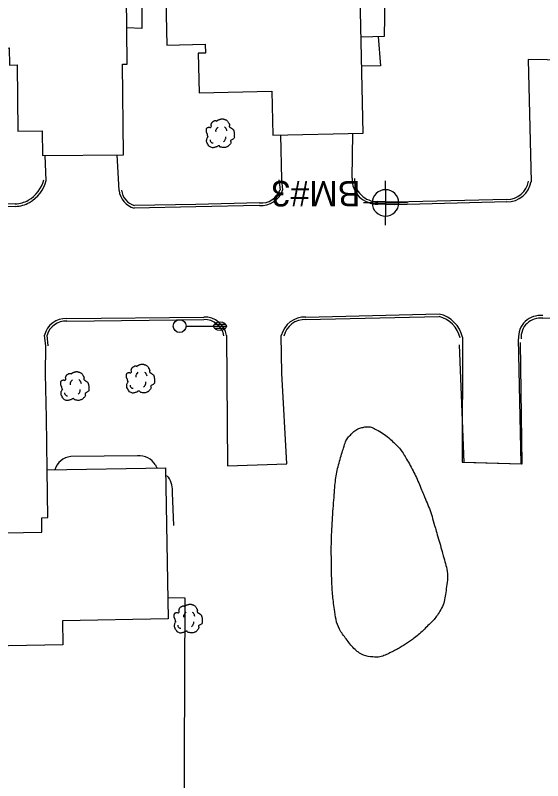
# Model space of a CAD drawing. Extents: x 2145380 to 2156929, y 139568 to 149130.
# Drawn here: x 2150403.3 to 2150527.5, y 144116.2 to 144296.4 of the extents above; entities that cross this region are included whole.
import ezdxf

# ---------------------------------------------------------------- set-up
doc = ezdxf.new("R2010")
doc.units = 0
for name, color, linetype in [('SURV_Benchmark', 7, 'Continuous'), ('SURV_Text', 7, 'Continuous'), ('TOPO_Asphalt', 7, 'Continuous'), ('TOPO_Building', 7, 'Continuous'), ('TOPO_Concrete', 7, 'Continuous'), ('TOPO_Curb Back', 7, 'Continuous'), ('TOPO_Fence', 7, 'Continuous'), ('TOPO_Light Pole', 7, 'Continuous'), ('TOPO_Tree', 7, 'Continuous'), ('TOPO_Tree Line', 7, 'Continuous'), ('TOPO_Wall Freestanding', 7, 'Continuous')]:
    doc.layers.add(name, color=color, linetype=linetype)

# ---------------------------------------------------------------- blocks, each defined once
blk = doc.blocks.new('LP')
at = {"layer": 'TOPO_Light Pole'}
blk.add_line((3.81, 0), (20.32, 0), dxfattribs=at)
for points in [[(20.32, 0), (27.94, 0)], [(20.32, 0), (23.5, 0)], [(20.83, 1.27), (27.43, 1.27)], [(20.83, 1.27), (23.5, 1.27)], [(23.71, 1.27), (27.43, 1.27)], [(23.71, 0), (27.94, 0)], [(20.83, -1.27), (27.43, -1.27)], [(20.83, -1.27), (23.5, -1.27)], [(23.71, -1.27), (27.43, -1.27)]]:
    blk.add_lwpolyline(points, dxfattribs=at)
blk.add_circle((0, 0), 3.81, dxfattribs=at)
blk.add_ellipse((24.13, 0), major_axis=(3.81, 0), ratio=0.666667, dxfattribs=at)
blk = doc.blocks.new('TREE')
at = {"layer": 'TOPO_Tree'}
for points in [[(-14.07, -0.4), (-14.17, 0.5), (-14.37, 1.38), (-14.6, 2.25), (-14.84, 3.17), (-15.47, 3.96), (-15.66, 4.9), (-15.8, 5.59), (-15.71, 6.31), (-15.66, 7.01), (-15.6, 7.91), (-15.72, 8.8), (-15.13, 9.66), (-14.62, 10.42), (-13.76, 10.49), (-13.02, 10.72), (-12.18, 10.98), (-11.06, 10), (-10.37, 10.72), (-9.4, 11.74), (-10.29, 13.28), (-9.84, 14.42), (-9.56, 15.15), (-9.32, 15.89), (-8.78, 16.54), (-8.18, 17.26), (-7.5, 17.68), (-6.67, 18.13), (-6.14, 18.41), (-5.61, 18.61), (-5.08, 18.66), (-4.55, 18.71), (-4.02, 18.54), (-3.49, 18.13)], [(-3.49, 17.6), (-3.07, 18.27), (-2.58, 18.8), (-1.9, 19.19), (-1.05, 19.68), (-0.19, 19.96), (0.74, 20.24), (1.62, 20.51), (2.51, 20.82), (3.39, 20.77), (4.1, 20.73), (4.8, 20.47), (5.51, 20.24), (6.43, 19.95), (7.32, 19.73), (8.15, 19.19), (9.36, 18.4), (10.02, 17.21), (10.8, 16.01), (11.24, 15.33), (11.58, 14.62), (11.86, 13.89), (12.17, 13.08), (11.37, 12.02), (11.86, 11.25), (12, 11.03), (12.18, 10.86), (12.39, 10.72), (12.91, 10.35), (13.45, 10.02), (13.97, 9.66), (14.7, 9.16), (15.41, 8.68), (16.09, 8.07), (16.7, 7.53), (16.93, 6.73), (17.15, 5.95), (17.59, 4.38), (17.71, 2.77), (17.68, 1.19), (17.65, -0.25), (17.83, -2.22), (16.62, -3.04), (15.47, -3.83), (14.31, -4.58), (13.16, -5.35)], [(-4.21, 5.09), (-4.46, 6.09), (-4.3, 7.21), (-3.84, 8.21), (-3.33, 9.34), (-2.71, 10.27), (-1.64, 10.97)], [(5.89, 11.15), (6.5, 10.68), (6.96, 10.17), (7.36, 9.5), (7.93, 8.56), (8.31, 7.6), (8.46, 6.56)], [(13.16, -5.34), (13.25, -5.81), (13.36, -6.28), (13.45, -6.75), (13.76, -8.52), (12.24, -10.03), (10.8, -11.51), (9.98, -12.34), (9.13, -12.77), (8.15, -13.1), (5.97, -13.83), (3.32, -13.56), (1.27, -13.1), (0.49, -12.92), (-0.06, -11.44), (-0.84, -11.51), (-2.04, -11.61), (-3.28, -12.78), (-4.55, -13.1), (-6.06, -13.47), (-7.77, -14.03), (-9.31, -13.62), (-11.36, -13.09), (-12.84, -11.41), (-14.07, -9.39), (-15.32, -7.35), (-15.61, -5.13), (-15.13, -3.04), (-14.87, -1.89), (-13.91, -0.75), (-13.54, 0.13)], [(-11.38, -4.46), (-11.47, -5.41), (-11.03, -6.32), (-10.09, -7.22), (-9.3, -7.97), (-8.49, -8.26), (-7.7, -8.14)], [(4.79, -6.29), (5.71, -5.66), (6.3, -4.92), (6.81, -3.91), (7.36, -2.81), (7.63, -1.7), (7.54, -0.6)]]:
    blk.add_open_spline(points, degree=3, dxfattribs=at)
blk = doc.blocks.new('BM')
at = {"layer": 'SURV_Benchmark'}
for p, q in [((0, 2.49), (0, 4.15)), ((-2.49, 0), (-4.16, 0)), ((4.16, 0), (2.49, 0)), ((0, -4.16), (0, -2.49))]:
    blk.add_line(p, q, dxfattribs=at)
for points in [[(0, 2.49), (0, 2.49), (0, 0), (2.49, 0), (2.49, 0), (2.49, 0)], [(0, 2.49), (0, 2.49), (0, 0), (2.49, 0), (2.49, 0), (2.49, 0), (2.49, 0)], [(-2.5, 0), (-2.49, 0), (0, 0), (0, -2.49), (0, -2.49)], [(-2.5, 0), (-2.49, 0), (0, 0), (0, -2.49), (0, -2.49)]]:
    blk.add_lwpolyline(points, dxfattribs=at)
for start, end in [(90.0638, 180.0068), (0.0638, 90.0068), (0.0638, 90.0068), (180.0638, 270.0068), (180.0638, 270.0068), (269.9472, 359.9927)]:
    blk.add_arc((0, 0), 2.5, start, end, dxfattribs=at)

msp = doc.modelspace()

# ---------------------------------------------------------------- linework, layer by layer
at = {"layer": 'TOPO_Asphalt'}
for p, q in [((2150465.79, 144268.25), (2150466, 144257.73)), ((2150482.61, 144258.07), (2150482.77, 144268.62)), ((2150410.6, 144257.51), (2150410.34, 144263.41)), ((2150427.75, 144255.16), (2150427.32, 144263.58))]:
    msp.add_line(p, q, dxfattribs=at)
for points in [[(2150541.72, 144255.28), (2150541.74, 144263.92), (2150541.87, 144285.75), (2150524.11, 144286), (2150524.76, 144257.23)], [(2150453.06, 144221.05), (2150453.33, 144190.37), (2150467.3, 144190.8), (2150466.05, 144212.19), (2150465.96, 144221.01)], [(2150508.66, 144220.61), (2150508.55, 144191.2), (2150522.44, 144190.82), (2150521.8, 144220.24)], [(2150410.82, 144189.37), (2150410.69, 144201.64), (2150410.42, 144212.02), (2150410.51, 144218.51)]]:
    msp.add_lwpolyline(points, dxfattribs=at)
at = {"layer": 'TOPO_Building'}
for points in [[(2150485.27, 144268.68), (2150483.7, 144340.46), (2150489.26, 144340.58), (2150489, 144352.33), (2150484.18, 144352.23), (2150484.16, 144353.34), (2150453.41, 144352.67), (2150453.92, 144329.04), (2150438.12, 144328.7), (2150438.98, 144289.42), (2150448.05, 144289.62), (2150448.1, 144287.52), (2150446.39, 144287.48), (2150446.6, 144278.17), (2150463.72, 144278.54), (2150463.95, 144268.21)], [(2150428.82, 144263.6), (2150428.6, 144284.94), (2150429.67, 144284.95), (2150429.43, 144309.11), (2150418.82, 144309), (2150418.67, 144323.49), (2150410.81, 144323.41), (2150410.8, 144324.17), (2150379.15, 144323.85), (2150379.5, 144288.53), (2150401.9, 144288.76), (2150401.94, 144284.72), (2150403.8, 144284.74), (2150403.95, 144269.18), (2150409.66, 144269.24), (2150409.72, 144263.41)], [(2150392.2, 144174.38), (2150409.61, 144174.69), (2150409.55, 144178.13), (2150411.01, 144178.16), (2150410.82, 144189.37), (2150438.66, 144189.86), (2150439.3, 144154.33), (2150414.42, 144153.88), (2150414.53, 144148.16), (2150393.07, 144147.78), (2150392.87, 144159.04), (2150391.96, 144159.02), (2150391.8, 144167.77), (2150392.32, 144167.78)]]:
    msp.add_lwpolyline(points, close=True, dxfattribs=at)
at = {"layer": 'TOPO_Concrete'}
for points in [[(2150488.79, 144291.48), (2150489.29, 144284.52), (2150484.92, 144284.49)], [(2150522.2, 144219.4), (2150522.56, 144190.73), (2150509, 144191.1), (2150507.95, 144218.84)]]:
    msp.add_lwpolyline(points, dxfattribs=at)
at = {"layer": 'TOPO_Curb Back'}
for points in [[(2150465.41, 144257.66), (2150465.66, 144255.31)], [(2150466, 144257.73), (2150466.27, 144255.24)], [(2150403.33, 144252.05), (2150380.43, 144251.31), (2150376.14, 144251.31)], [(2150460.81, 144252.27), (2150445.86, 144251.91), (2150431.37, 144251.62)], [(2150519.06, 144253.08), (2150492.7, 144252.41), (2150488.66, 144252.58)], [(2150519.07, 144252.48), (2150492.69, 144251.81), (2150488.66, 144251.98)], [(2150403.35, 144251.45), (2150380.44, 144250.71), (2150376.16, 144250.71)], [(2150460.79, 144251.67), (2150445.87, 144251.31), (2150431.29, 144251.02)], [(2150415.45, 144225.04), (2150447.73, 144225.39)], [(2150415.45, 144224.44), (2150447.74, 144224.79)], [(2150471.75, 144225.38), (2150503.17, 144226.1)], [(2150471.75, 144224.78), (2150503.11, 144225.5)], [(2150527.51, 144225.11), (2150558.34, 144225.96)], [(2150410.51, 144218.51), (2150410.21, 144221.15)], [(2150411.1, 144218.58), (2150410.82, 144221.1)]]:
    msp.add_lwpolyline(points, dxfattribs=at)
for centre, radius, start, end in [((2150402.38, 144259.69), 7.9, 300.5561, 345.1621), ((2150402.38, 144259.69), 8.5, 300.4829, 345.1621), ((2150488.47, 144257.84), 5.86, 177.7965, 271.8803), ((2150488.47, 144257.84), 5.26, 177.7965, 272.1178), ((2150519.09, 144258.24), 5.16, 269.7006, 350.308), ((2150519.09, 144258.24), 5.76, 269.7945, 350.308), ((2150432.67, 144255.79), 4.96, 187.2417, 253.8013), ((2150432.67, 144255.79), 4.36, 187.2417, 252.64), ((2150461.24, 144256.97), 5.32, 265.2017, 341.0317), ((2150461.24, 144256.97), 4.72, 264.8204, 339.4562), ((2150403.07, 144259.01), 6.97, 272.1205, 298.4766), ((2150403.07, 144259.01), 7.57, 272.1096, 298.5592), ((2150415.27, 144219.8), 5.24, 88.0099, 165.13), ((2150447.87, 144220.12), 5.27, 10.1271, 91.541), ((2150447.87, 144220.12), 4.67, 10.1271, 91.598), ((2150471.55, 144219.63), 5.76, 87.9526, 166.0898), ((2150471.55, 144219.63), 5.16, 87.7621, 166.0898), ((2150501.49, 144218.93), 6.76, 13.1474, 76.2066), ((2150501.49, 144218.93), 7.36, 13.1474, 76.8389), ((2150526.95, 144220.59), 5.15, 83.4622, 183.8003), ((2150526.95, 144220.59), 4.55, 82.9424, 183.8003), ((2150415.27, 144219.8), 4.64, 87.846, 163.776)]:
    msp.add_arc(centre, radius, start, end, dxfattribs=at)
at = {"layer": 'TOPO_Fence'}
for points in [[(2150484.77, 144291.37), (2150490.29, 144291.53), (2150490.95, 144331.48)], [(2150433.39, 144322.94), (2150433.15, 144293.31), (2150429.59, 144293.48)], [(2150439.22, 144159.3), (2150443.26, 144159.27), (2150442.96, 144084.3), (2150387.35, 144083.83), (2150387.67, 144149.58), (2150385.55, 144149.5)]]:
    msp.add_lwpolyline(points, dxfattribs=at)
at = {"layer": 'TOPO_Tree Line'}
msp.add_open_spline([(2150503.41, 144171.65), (2150502.8, 144173.75), (2150502.19, 144175.85), (2150501.58, 144177.96), (2150501.04, 144179.82), (2150500.26, 144181.6), (2150499.54, 144183.4), (2150498.18, 144186.78), (2150496.61, 144190.01), (2150494.72, 144193.16), (2150494.06, 144194.27), (2150493.17, 144195.13), (2150492.23, 144196.03), (2150490.93, 144197.28), (2150489.56, 144198.24), (2150487.96, 144199.08), (2150487.12, 144199.52), (2150486.1, 144199.6), (2150485.22, 144199.4), (2150484.21, 144199.16), (2150483.26, 144198.68), (2150482.45, 144197.83), (2150481.57, 144196.92), (2150481.05, 144196), (2150480.71, 144194.9), (2150479.64, 144191.43), (2150478.78, 144187.99), (2150478.5, 144184.43), (2150478.07, 144178.9), (2150477.71, 144173.38), (2150477.75, 144167.85), (2150477.76, 144165.88), (2150477.83, 144163.91), (2150477.92, 144161.95), (2150478, 144160.16), (2150478.21, 144158.39), (2150478.45, 144156.61), (2150478.78, 144154.1), (2150479.52, 144151.85), (2150481.23, 144149.58), (2150482.98, 144147.26), (2150485.25, 144145.53), (2150487.7, 144145.33), (2150488.86, 144145.24), (2150490.17, 144145.62), (2150491.28, 144146.17), (2150492.37, 144146.72), (2150493.43, 144147.25), (2150494.46, 144147.9), (2150495.43, 144148.51), (2150496.37, 144149.12), (2150497.28, 144149.81), (2150498.55, 144150.78), (2150499.66, 144151.88), (2150500.79, 144153.01), (2150501.73, 144153.95), (2150502.55, 144154.9), (2150503.26, 144156.09), (2150504.15, 144157.6), (2150504.53, 144159.23), (2150504.74, 144160.9), (2150505, 144162.9), (2150505.24, 144165.01), (2150504.71, 144166.96), (2150504.28, 144168.52), (2150503.84, 144170.09), (2150503.41, 144171.65)], degree=3, dxfattribs=at)
at = {"layer": 'TOPO_Wall Freestanding'}
for points in [[(2150432.09, 144192.69), (2150416.37, 144192.52)], [(2150440.69, 144176.29), (2150440.31, 144183.95)]]:
    msp.add_lwpolyline(points, dxfattribs=at)
for centre, radius, start, end in [((2150416.77, 144188.3), 4.24, 95.4264, 164.9777), ((2150432.59, 144188.43), 4.28, 29.716, 96.5851), ((2150441.2, 144192.8), 5.38, 204.5853, 213.4281), ((2150431.96, 144176.92), 13.08, 55.2548, 59.0205), ((2150434.81, 144184.59), 5.54, 353.4273, 33.7156)]:
    msp.add_arc(centre, radius, start, end, dxfattribs=at)

# ---------------------------------------------------------------- block references
at = {"layer": 'SURV_Benchmark', "xscale": 1.25, "yscale": 1.25}
msp.add_blockref('BM', (2150490.5, 144252.25), dxfattribs=at)
at = {"layer": 'TOPO_Light Pole', "xscale": 0.39370000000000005, "yscale": 0.3937000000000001}
msp.add_blockref('LP', (2150442.03, 144223.24), dxfattribs=at)
at = {"layer": 'TOPO_Tree', "xscale": 0.19685000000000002, "yscale": 0.19685000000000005}
for p in [(2150451.42, 144267.97), (2150432.61, 144210.21), (2150417.15, 144208.44), (2150443.85, 144153.69)]:
    msp.add_blockref('TREE', p, dxfattribs=at)

# ---------------------------------------------------------------- texts
at = {"layer": 'SURV_Text'}
msp.add_text('BM#3', height=6, rotation=180, dxfattribs=at).set_placement((2150484.59, 144257.43))

doc.saveas('drawing.dxf')
